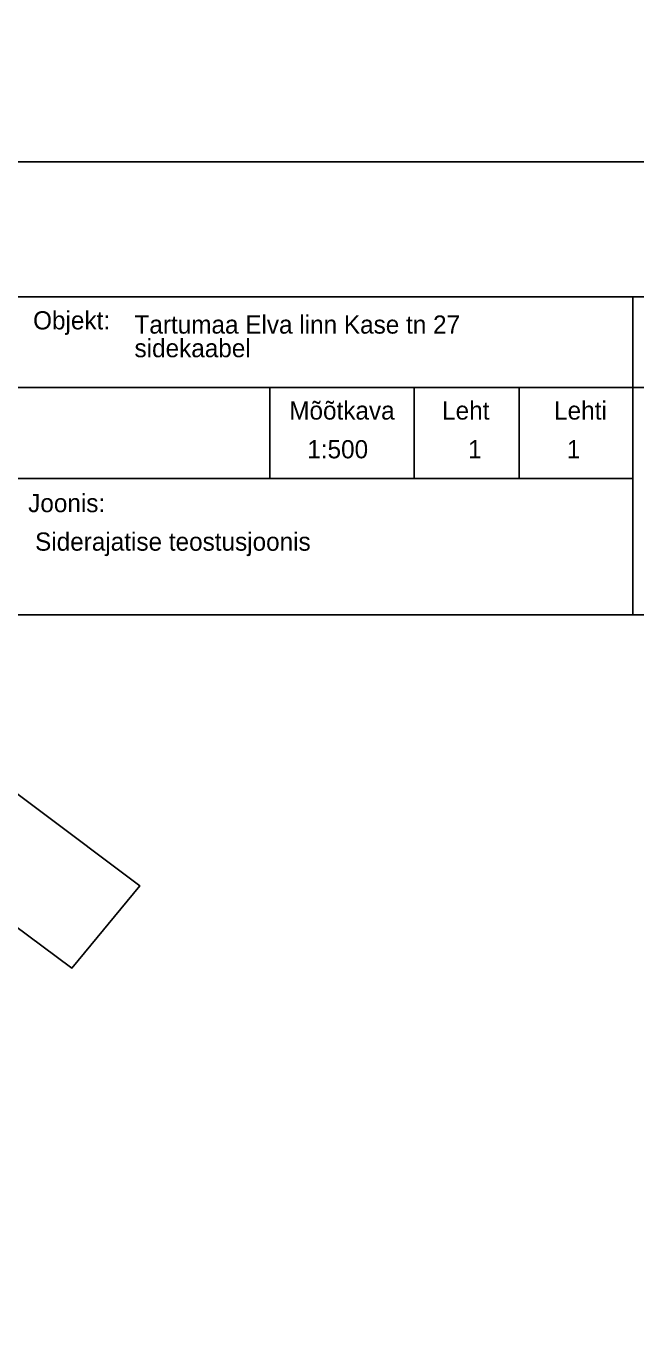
# Model space of a CAD drawing. Extents: x 640876 to 641182, y 6455704 to 6455993.
# Drawn here: x 640958.4 to 640991.9, y 6455746.4 to 6455818.5 of the extents above; entities that cross this region are included whole.
import ezdxf

# ---------------------------------------------------------------- set-up
doc = ezdxf.new("R2010")
doc.units = 0
doc.layers.add('PIIR', color=7, linetype='Continuous')
doc.layers.add('VORMISTUS', color=7, linetype='Continuous')

msp = doc.modelspace()

# ---------------------------------------------------------------- linework, layer by layer
at = {"layer": 'PIIR'}
msp.add_lwpolyline([(641037.5, 6455958.58), (641024.93, 6455943.02), (641012.36, 6455927.46), (640993.57, 6455904.12), (640971.01, 6455875.38), (640962.33, 6455865.02), (640876.41, 6455757.97), (640888.17, 6455749.25), (640894.56, 6455746.37), (640902.45, 6455758.84), (640915.55, 6455775.13), (640928.34, 6455790.92), (640960.9, 6455766.7), (640964.64, 6455771.22), (640941.6, 6455788.51), (640929.99, 6455798.13), (640933.13, 6455802.02), (640952.64, 6455826.1), (640977.72, 6455857.07), (640984.64, 6455865.92), (641005.01, 6455891.09), (641032.25, 6455870.2), (641049.71, 6455856.81)], dxfattribs=at)
at = {"layer": 'VORMISTUS'}
for p, q in [((640924.41, 6455803.627), (641016.602, 6455803.627)), ((640991.76, 6455803.624), (640991.763, 6455786.133)), ((640924.411, 6455798.631), (641016.602, 6455798.621)), ((640971.786, 6455798.604), (640971.781, 6455793.627)), ((640979.73, 6455798.625), (640979.729, 6455793.626)), ((640985.501, 6455798.624), (640985.5, 6455793.625)), ((640924.414, 6455793.625), (640991.762, 6455793.625)), ((640924.416, 6455786.126), (641016.602, 6455786.126))]:
    msp.add_line(p, q, dxfattribs=at)
for points in [[(640924.107, 6455786.126), (640924.107, 6455929.626), (641016.607, 6455929.626), (641016.607, 6455786.126)], [(641015.363, 6455786.126), (640924.416, 6455786.126), (640924.416, 6455811.035), (641015.363, 6455811.035)]]:
    msp.add_lwpolyline(points, close=True, dxfattribs=at)
msp.add_lwpolyline([(640924.416, 6455786.126), (641016.602, 6455786.126)], dxfattribs=at)

# ---------------------------------------------------------------- texts
for s, height, p in [('Objekt:', 0.9997, (640958.767, 6455801.827)), ('Tartumaa Elva linn Kase tn 27', 0.99972, (640964.347, 6455801.596)), ('sidekaabel', 0.9997, (640964.347, 6455800.297)), ('Mõõtkava', 0.9997, (640972.858, 6455796.867)), ('Leht', 0.9997, (640981.267, 6455796.867)), ('Lehti', 0.9997, (640987.427, 6455796.867)), ('1:500', 0.9997, (640973.851, 6455794.737)), ('1', 1, (640982.697, 6455794.737)), ('1', 1, (640988.127, 6455794.737)), ('Joonis:', 0.9997, (640958.497, 6455791.777)), ('Siderajatise teostusjoonis', 0.99972, (640958.877, 6455789.657))]:
    msp.add_text(s, height=height, rotation=359.99742, dxfattribs=at).set_placement(p)

doc.saveas('drawing.dxf')
